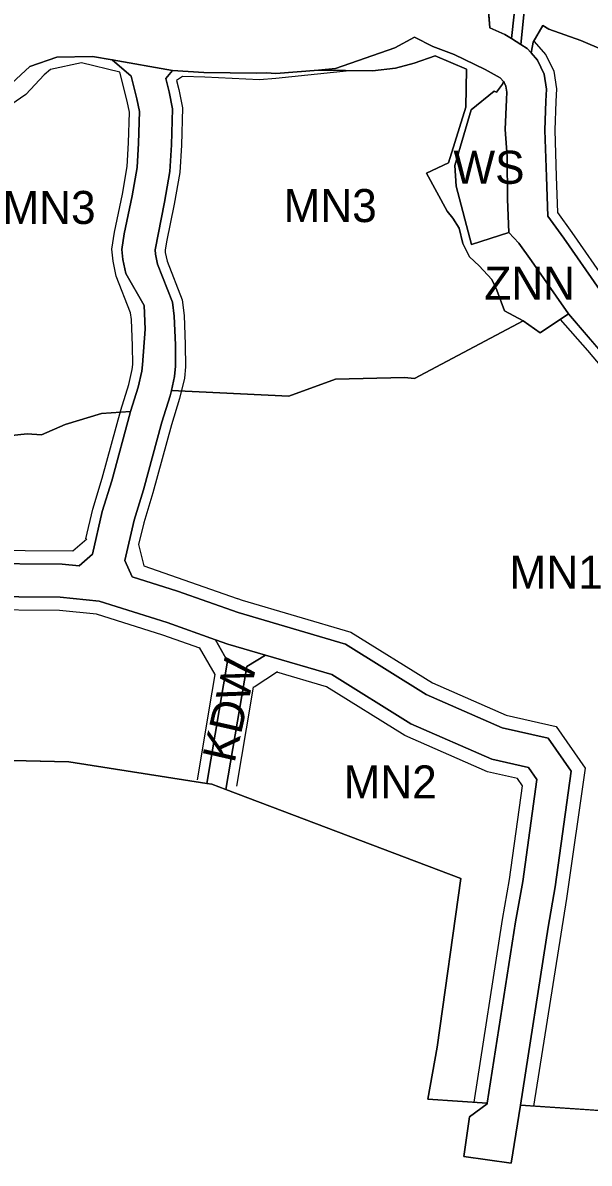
# Model space of a CAD drawing. Extents: x 7417187 to 7419415, y 5539178 to 5540826.
# Drawn here: x 7418228.7 to 7418400.2, y 5539585.1 to 5539930.4 of the extents above; entities that cross this region are included whole.
import ezdxf

# ---------------------------------------------------------------- set-up
doc = ezdxf.new("R2010")
doc.units = 0
for name, color, linetype in [('linie_rozgraniczajace', 7, 'Continuous'), ('linie_zabudowy_nieprzekraczalne', 7, 'Continuous'), ('oznaczenia_przeznaczen', 7, 'Continuous')]:
    doc.layers.add(name, color=color, linetype=linetype)

msp = doc.modelspace()

# ---------------------------------------------------------------- linework, layer by layer
at = {"layer": 'linie_rozgraniczajace'}
for p, q in [((7418369.25, 5539940), (7418370.12, 5539928.88)), ((7418347.31, 5539926.05), (7418341.35, 5539922.76)), ((7418352.83, 5539923.23), (7418347.31, 5539926.05)), ((7418370.12, 5539928.88), (7418374.72, 5539926.81)), ((7418374.72, 5539926.81), (7418376.67, 5539925.59)), ((7418341.35, 5539922.76), (7418323.41, 5539916.51)), ((7418359.35, 5539920.74), (7418352.83, 5539923.23)), ((7418376.67, 5539925.59), (7418379.52, 5539923.81)), ((7418379.52, 5539923.81), (7418381.42, 5539922.63)), ((7418381.42, 5539922.63), (7418382.62, 5539921.27)), ((7418238.98, 5539919.96), (7418230.77, 5539917.17)), ((7418249.79, 5539920.17), (7418238.98, 5539919.96)), ((7418255.69, 5539919.14), (7418249.79, 5539920.17)), ((7418274.06, 5539915.93), (7418255.69, 5539919.14)), ((7418368.69, 5539916.21), (7418359.35, 5539920.74)), ((7418382.62, 5539921.27), (7418384.59, 5539919.05)), ((7418230.77, 5539917.17), (7418223.92, 5539910.78)), ((7418283.48, 5539915.29), (7418274.06, 5539915.93)), ((7418318.19, 5539916.07), (7418305.29, 5539914.99)), ((7418323.41, 5539916.51), (7418318.19, 5539916.07)), ((7418373.3, 5539913.69), (7418368.69, 5539916.21)), ((7418384.59, 5539919.05), (7418386.64, 5539914.8)), ((7418299.44, 5539915.12), (7418283.48, 5539915.29)), ((7418302.46, 5539915.24), (7418299.44, 5539915.12)), ((7418305.29, 5539914.99), (7418302.46, 5539915.24)), ((7418374.3, 5539912.57), (7418373.3, 5539913.69)), ((7418374.5, 5539912.34), (7418374.3, 5539912.57)), ((7418375.03, 5539911.24), (7418374.5, 5539912.34)), ((7418386.64, 5539914.8), (7418387.3, 5539910.28)), ((7418375.3, 5539909.4), (7418375.03, 5539911.24)), ((7418375.14, 5539907.17), (7418375.3, 5539909.4)), ((7418387.3, 5539910.28), (7418387.13, 5539906.65)), ((7418374.83, 5539898.03), (7418375.14, 5539907.17)), ((7418387.13, 5539906.65), (7418386.84, 5539897.92)), ((7418375.38, 5539889.88), (7418374.83, 5539898.03)), ((7418386.84, 5539897.92), (7418387.26, 5539883.72)), ((7418375.5, 5539876.96), (7418375.38, 5539889.88)), ((7418387.26, 5539883.72), (7418387.7, 5539871.79)), ((7418375.87, 5539866.85), (7418375.5, 5539876.96)), ((7418387.7, 5539871.79), (7418392.53, 5539865.18)), ((7418378.9, 5539863.61), (7418375.87, 5539866.85)), ((7418392.53, 5539865.18), (7418403.36, 5539849.67)), ((7418382.73, 5539858.26), (7418378.9, 5539863.61)), ((7418393.93, 5539842.31), (7418382.73, 5539858.26)), ((7418427.7, 5539802.79), (7418393.93, 5539842.31)), ((7418117.97, 5539709.49), (7418242.64, 5539706.65)), ((7418242.64, 5539706.65), (7418284.43, 5539700.08)), ((7418284.43, 5539700.08), (7418285.91, 5539699.85)), ((7418285.91, 5539699.85), (7418290.2, 5539698.23)), ((7418290.2, 5539698.23), (7418361.32, 5539671.28)), ((7418361.32, 5539671.28), (7418354.15, 5539620.25)), ((7418354.15, 5539620.25), (7418351.31, 5539604.49)), ((7418351.31, 5539604.49), (7418369.37, 5539603.28)), ((7418369.33, 5539603.04), (7418363.97, 5539599.1)), ((7418369.37, 5539603.28), (7418369.33, 5539603.04)), ((7418376.64, 5539585.07), (7418379.39, 5539602.6)), ((7418379.39, 5539602.6), (7418441.73, 5539598.41)), ((7418363.97, 5539599.1), (7418362.26, 5539587.12)), ((7418362.26, 5539587.12), (7418376.64, 5539585.07))]:
    msp.add_line(p, q, dxfattribs=at)
for points in [[(7418376.67, 5539925.59), (7418374.72, 5539926.81), (7418370.12, 5539928.88), (7418369.25, 5539940), (7418379.12, 5539947.79)], [(7418379.52, 5539923.81), (7418376.67, 5539925.59), (7418379.12, 5539947.79), (7418381.45, 5539949.61), (7418382.19, 5539950.06)], [(7418374.3, 5539912.57), (7418374.02, 5539911.82), (7418372.21, 5539909.41), (7418371.42, 5539909.67), (7418364.52, 5539904.05), (7418359.57, 5539887.17), (7418359.99, 5539880.92), (7418364.54, 5539863.26), (7418375.87, 5539866.85), (7418378.9, 5539863.61), (7418382.73, 5539858.26), (7418393.93, 5539842.31), (7418385.4, 5539836.51), (7418380.19, 5539840.19), (7418374.59, 5539843.13), (7418372.26, 5539849.38), (7418370.7, 5539852.68), (7418366.91, 5539856.8), (7418363.95, 5539859.53), (7418361.97, 5539863.59), (7418360.88, 5539868.2), (7418358.95, 5539871.23), (7418357.18, 5539873.36), (7418350.98, 5539884.82), (7418357.63, 5539887.94), (7418362.85, 5539904.84), (7418363.12, 5539916.37), (7418353.6, 5539920.43), (7418347.22, 5539918.12), (7418341.59, 5539916.63), (7418334.57, 5539915.8), (7418318.19, 5539916.07), (7418323.41, 5539916.51), (7418341.35, 5539922.76), (7418347.31, 5539926.05), (7418352.83, 5539923.23), (7418359.35, 5539920.74), (7418368.69, 5539916.21), (7418373.3, 5539913.69)], [(7418380.19, 5539840.19), (7418347.27, 5539822.72), (7418344.26, 5539823.01), (7418323.35, 5539822.48), (7418309.23, 5539817.29), (7418273.66, 5539819), (7418274.66, 5539823.24), (7418274.96, 5539826.37), (7418274.88, 5539832.88), (7418274.53, 5539841.56), (7418274.03, 5539845.76), (7418269.49, 5539857.34), (7418268.87, 5539860.34), (7418268.72, 5539861.59), (7418271.61, 5539876.08), (7418273.22, 5539885.36), (7418273.71, 5539893.47), (7418274, 5539904.37), (7418272.99, 5539909.53), (7418271.99, 5539913.5), (7418274.06, 5539915.93), (7418283.48, 5539915.29), (7418299.44, 5539915.12), (7418302.46, 5539915.24), (7418305.29, 5539914.99), (7418318.19, 5539916.07), (7418334.57, 5539915.8), (7418341.59, 5539916.63), (7418347.22, 5539918.12), (7418353.6, 5539920.43), (7418363.12, 5539916.37), (7418362.85, 5539904.84), (7418357.63, 5539887.94), (7418350.98, 5539884.82), (7418357.18, 5539873.36), (7418358.95, 5539871.23), (7418360.88, 5539868.2), (7418361.97, 5539863.59), (7418363.95, 5539859.53), (7418366.91, 5539856.8), (7418370.7, 5539852.68), (7418372.26, 5539849.38), (7418374.59, 5539843.13)], [(7418375.87, 5539866.85), (7418364.54, 5539863.26), (7418359.99, 5539880.92), (7418359.57, 5539887.17), (7418364.52, 5539904.05), (7418371.42, 5539909.67), (7418372.21, 5539909.41), (7418374.02, 5539911.82), (7418374.3, 5539912.57), (7418374.5, 5539912.34), (7418375.03, 5539911.24), (7418375.3, 5539909.4), (7418375.14, 5539907.17), (7418374.83, 5539898.03), (7418375.38, 5539889.88), (7418375.5, 5539876.96)], [(7418143.19, 5539767.85), (7418145.28, 5539783.81), (7418145.8, 5539788.38), (7418147.31, 5539793.29), (7418147.8, 5539804.87), (7418168.02, 5539804.71), (7418214.86, 5539804.35), (7418230.03, 5539805.96), (7418234.36, 5539805.67), (7418241.45, 5539808.76), (7418252.53, 5539812.06), (7418261.32, 5539812.68), (7418261.19, 5539812.28), (7418255.59, 5539791.7), (7418252.73, 5539782.38), (7418249.79, 5539769.47), (7418245.72, 5539765.92), (7418240.54, 5539766.43), (7418214.71, 5539766.66), (7418185.74, 5539765.64), (7418165.41, 5539762.82), (7418156.27, 5539764.29)], [(7418287.08, 5539743.57), (7418290.72, 5539737.09), (7418284.43, 5539700.08), (7418242.64, 5539706.65), (7418117.97, 5539709.49), (7418042.23, 5539720.7), (7418011.72, 5539719.57), (7418012.2, 5539730.83), (7418012.17, 5539742.43), (7418011.89, 5539749.7), (7418020.58, 5539752.31), (7418043.03, 5539757.25), (7418056.24, 5539756.46), (7418078.91, 5539754.39), (7418105.15, 5539753.62), (7418129.13, 5539756.37), (7418141.85, 5539757.86), (7418154.16, 5539754.5), (7418165.3, 5539752.71), (7418186.6, 5539755.66), (7418214.84, 5539756.66), (7418240.01, 5539756.43), (7418251.75, 5539755.28), (7418272.38, 5539748.77)], [(7418302.23, 5539738.9), (7418296.53, 5539735.49), (7418290.2, 5539698.23), (7418285.91, 5539699.85), (7418284.43, 5539700.08), (7418290.72, 5539737.09), (7418287.08, 5539743.57), (7418290.79, 5539742.26)], [(7418369.37, 5539603.28), (7418351.31, 5539604.49), (7418354.15, 5539620.25), (7418361.32, 5539671.28), (7418290.2, 5539698.23), (7418296.53, 5539735.49), (7418302.23, 5539738.9), (7418322.28, 5539733.01), (7418346.23, 5539718.11), (7418370.7, 5539707.41), (7418381.81, 5539704.85), (7418384.33, 5539701.25), (7418380.09, 5539670.32), (7418377.96, 5539658.18)]]:
    msp.add_lwpolyline(points, close=True, dxfattribs=at)
for points in [[(7418411.41, 5539919.15), (7418397.68, 5539924.98), (7418388.03, 5539928.44), (7418386.17, 5539929.57), (7418383.25, 5539924.52), (7418382.79, 5539921.78), (7418382.62, 5539921.27), (7418381.42, 5539922.63), (7418379.52, 5539923.81), (7418382.19, 5539950.06)], [(7418403.36, 5539849.67), (7418392.53, 5539865.18), (7418387.7, 5539871.79), (7418387.26, 5539883.72), (7418386.84, 5539897.92), (7418387.13, 5539906.65), (7418387.3, 5539910.28), (7418386.64, 5539914.8), (7418384.59, 5539919.05), (7418382.62, 5539921.27), (7418382.79, 5539921.78), (7418383.25, 5539924.52), (7418386.17, 5539929.57), (7418388.03, 5539928.44), (7418397.68, 5539924.98), (7418411.41, 5539919.15)], [(7418214.71, 5539766.66), (7418240.54, 5539766.43), (7418245.72, 5539765.92), (7418249.79, 5539769.47), (7418252.73, 5539782.38), (7418255.59, 5539791.7), (7418261.19, 5539812.28), (7418261.32, 5539812.68), (7418263.63, 5539820.03), (7418264.77, 5539824.87), (7418264.96, 5539826.79), (7418265.69, 5539837.65), (7418265.42, 5539844.74), (7418259.88, 5539854.48), (7418258.99, 5539858.71), (7418258.62, 5539861.79), (7418259.38, 5539866.45), (7418261.78, 5539877.96), (7418263.27, 5539886.52), (7418263.71, 5539893.91), (7418263.98, 5539903.54), (7418263.23, 5539907.35), (7418261.5, 5539914.22), (7418255.69, 5539919.14), (7418274.06, 5539915.93), (7418271.99, 5539913.5), (7418272.99, 5539909.53), (7418274, 5539904.37), (7418273.71, 5539893.47), (7418273.22, 5539885.36), (7418271.61, 5539876.08), (7418268.72, 5539861.59), (7418268.87, 5539860.34), (7418269.49, 5539857.34), (7418274.03, 5539845.76), (7418274.53, 5539841.56), (7418274.88, 5539832.88), (7418274.96, 5539826.37), (7418274.66, 5539823.24), (7418273.66, 5539819), (7418273.28, 5539817.38), (7418270.79, 5539809.46), (7418265.2, 5539788.92), (7418262.39, 5539779.77), (7418259.55, 5539767.61), (7418261.78, 5539762.6), (7418275.55, 5539758.26), (7418293.86, 5539751.78), (7418326.4, 5539742.22), (7418350.9, 5539726.98), (7418373.85, 5539716.95), (7418387.8, 5539713.73), (7418394.78, 5539703.79), (7418389.97, 5539668.78), (7418387.83, 5539656.54), (7418379.39, 5539602.6), (7418376.64, 5539585.07), (7418362.26, 5539587.12), (7418363.97, 5539599.1), (7418369.33, 5539603.04), (7418369.37, 5539603.28), (7418377.96, 5539658.18), (7418380.09, 5539670.32), (7418384.33, 5539701.25), (7418381.81, 5539704.85), (7418370.7, 5539707.41), (7418346.23, 5539718.11), (7418322.28, 5539733.01), (7418302.23, 5539738.9), (7418290.79, 5539742.26), (7418287.08, 5539743.57), (7418272.38, 5539748.77), (7418251.75, 5539755.28), (7418240.01, 5539756.43), (7418214.84, 5539756.66)], [(7418223.92, 5539910.78), (7418230.77, 5539917.17), (7418238.98, 5539919.96), (7418249.79, 5539920.17), (7418255.69, 5539919.14), (7418261.5, 5539914.22), (7418263.23, 5539907.35), (7418263.98, 5539903.54), (7418263.71, 5539893.91), (7418263.27, 5539886.52), (7418261.78, 5539877.96), (7418259.38, 5539866.45), (7418258.62, 5539861.79), (7418258.99, 5539858.71), (7418259.88, 5539854.48), (7418265.42, 5539844.74), (7418265.69, 5539837.65), (7418264.96, 5539826.79), (7418264.77, 5539824.87), (7418263.63, 5539820.03), (7418261.32, 5539812.68), (7418252.53, 5539812.06), (7418241.45, 5539808.76), (7418234.36, 5539805.67), (7418230.03, 5539805.96), (7418214.86, 5539804.35)], [(7418441.73, 5539598.41), (7418379.39, 5539602.6), (7418387.83, 5539656.54), (7418389.97, 5539668.78), (7418394.78, 5539703.79), (7418387.8, 5539713.73), (7418373.85, 5539716.95), (7418350.9, 5539726.98), (7418326.4, 5539742.22), (7418293.86, 5539751.78), (7418275.55, 5539758.26), (7418261.78, 5539762.6), (7418259.55, 5539767.61), (7418262.39, 5539779.77), (7418265.2, 5539788.92), (7418270.79, 5539809.46), (7418273.28, 5539817.38), (7418273.66, 5539819), (7418309.23, 5539817.29), (7418323.35, 5539822.48), (7418344.26, 5539823.01), (7418347.27, 5539822.72), (7418380.19, 5539840.19), (7418385.4, 5539836.51), (7418393.93, 5539842.31), (7418427.7, 5539802.79)]]:
    msp.add_lwpolyline(points, dxfattribs=at)
at = {"layer": 'linie_zabudowy_nieprzekraczalne'}
for points in [[(7418383.45, 5539924.86), (7418387.11, 5539920.73), (7418389.54, 5539915.69), (7418390.31, 5539910.44), (7418390.13, 5539906.53), (7418389.84, 5539897.91), (7418390.26, 5539883.83), (7418390.66, 5539872.96), (7418394.98, 5539866.91), (7418405.82, 5539851.39)], [(7418237.01, 5539916.28), (7418235.12, 5539914.66), (7418229.63, 5539908.71), (7418202.5, 5539890.11), (7418197.31, 5539887.05)], [(7418246.48, 5539918.24), (7418237.01, 5539916.28)], [(7418258.01, 5539915.44), (7418246.48, 5539918.24)], [(7418327.62, 5539915.83), (7418305.32, 5539913.49)], [(7418247.73, 5539774.15), (7418249.83, 5539783.16), (7418252.72, 5539792.54), (7418258.32, 5539813.12), (7418260.74, 5539820.82), (7418261.81, 5539825.36), (7418261.96, 5539826.92), (7418261.89, 5539832.54), (7418261.56, 5539840.53), (7418261.32, 5539842.58), (7418256.99, 5539853.62), (7418256.03, 5539858.23), (7418255.59, 5539861.86), (7418256.43, 5539867), (7418258.84, 5539878.52), (7418260.29, 5539886.87), (7418260.72, 5539894.04), (7418260.97, 5539903.29), (7418260.31, 5539906.66), (7418258.01, 5539915.44)], [(7418275.22, 5539912.89), (7418275.92, 5539910.22), (7418277.01, 5539904.63), (7418276.71, 5539893.35), (7418276.2, 5539885.02), (7418274.56, 5539875.51), (7418272.16, 5539864.08), (7418271.75, 5539861.53), (7418271.83, 5539860.83), (7418272.38, 5539858.2), (7418276.97, 5539846.5), (7418277.52, 5539841.8), (7418277.88, 5539832.96), (7418277.97, 5539826.25), (7418277.63, 5539822.75), (7418276.18, 5539816.59), (7418273.67, 5539808.62), (7418268.08, 5539788.09), (7418265.29, 5539778.99), (7418263.75, 5539772.39)], [(7418277.08, 5539914.12), (7418275.22, 5539912.89)], [(7418283.78, 5539913.9), (7418277.08, 5539914.12)], [(7418300.39, 5539913.16), (7418283.78, 5539913.9)], [(7418305.32, 5539913.49), (7418300.39, 5539913.16)], [(7418416.72, 5539811.15), (7418399.82, 5539831.15), (7418391.53, 5539840.5)], [(7418243.78, 5539770.47), (7418248.05, 5539774.08)], [(7418214.79, 5539770.66), (7418243.78, 5539770.47)], [(7418263.75, 5539772.39), (7418265.35, 5539765.96)], [(7418265.35, 5539765.96), (7418293.65, 5539756.1)], [(7418282.26, 5539741.04), (7418271.11, 5539744.98), (7418250.95, 5539751.35), (7418239.8, 5539752.44), (7418214.89, 5539752.66), (7418186.95, 5539751.68), (7418165.26, 5539748.66), (7418153.31, 5539750.59), (7418141.55, 5539753.8), (7418129.6, 5539752.4)], [(7418293.68, 5539756.09), (7418295.1, 5539755.59), (7418328.06, 5539745.91)], [(7418328.06, 5539745.91), (7418352.77, 5539730.53), (7418375.12, 5539720.76), (7418390.19, 5539717.29)], [(7418286.98, 5539733.08), (7418282.17, 5539741.18)], [(7418281.57, 5539701.18), (7418285.99, 5539727.68), (7418286.98, 5539733.08)], [(7418305.78, 5539733.82), (7418298.8, 5539729.25)], [(7418378.52, 5539701.51), (7418369.44, 5539703.6), (7418344.36, 5539714.56), (7418320.63, 5539729.33), (7418305.58, 5539733.75)], [(7418298.48, 5539729.3), (7418297.81, 5539725.63), (7418293.41, 5539699.21)], [(7418390.19, 5539717.29), (7418399, 5539704.73)], [(7418399, 5539704.73), (7418393.41, 5539665.19), (7418383.37, 5539602.34)], [(7418365.37, 5539603.55), (7418374.02, 5539658.84), (7418376.14, 5539670.94), (7418380.04, 5539699.32)], [(7418380.04, 5539699.32), (7418378.52, 5539701.51)]]:
    msp.add_lwpolyline(points, dxfattribs=at)

# ---------------------------------------------------------------- texts
at = {"layer": 'oznaczenia_przeznaczen'}
for s, p in [('WS', (7418359.12, 5539881.63)), ('MN3', (7418222.49, 5539869.47)), ('MN3', (7418307.65, 5539870.04)), ('ZNN', (7418368.46, 5539846.57)), ('MN1', (7418376.1, 5539759.01)), ('MN2', (7418325.83, 5539695.52))]:
    msp.add_text(s, height=10, dxfattribs=at).set_placement(p)
msp.add_text('KDW', height=10, rotation=77.2476, dxfattribs=at).set_placement((7418292.75, 5539705.95))

doc.saveas('drawing.dxf')
